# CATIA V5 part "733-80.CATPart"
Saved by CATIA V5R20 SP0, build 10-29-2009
Part number: 733-80
Bounding box of the stored display mesh (mm): x -59 to 59, y -59 to 59, z -60 to 90
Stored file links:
  C:\Users\Utente\Desktop\IO LAVORO\3D X SITO CF\X SITO\733\733-80.CATPart
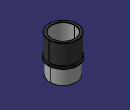
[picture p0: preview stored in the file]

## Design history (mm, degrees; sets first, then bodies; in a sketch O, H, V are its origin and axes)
Set1
  DatumSurface1 to DatumSurface25 "733-80"
Body1 (main body)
